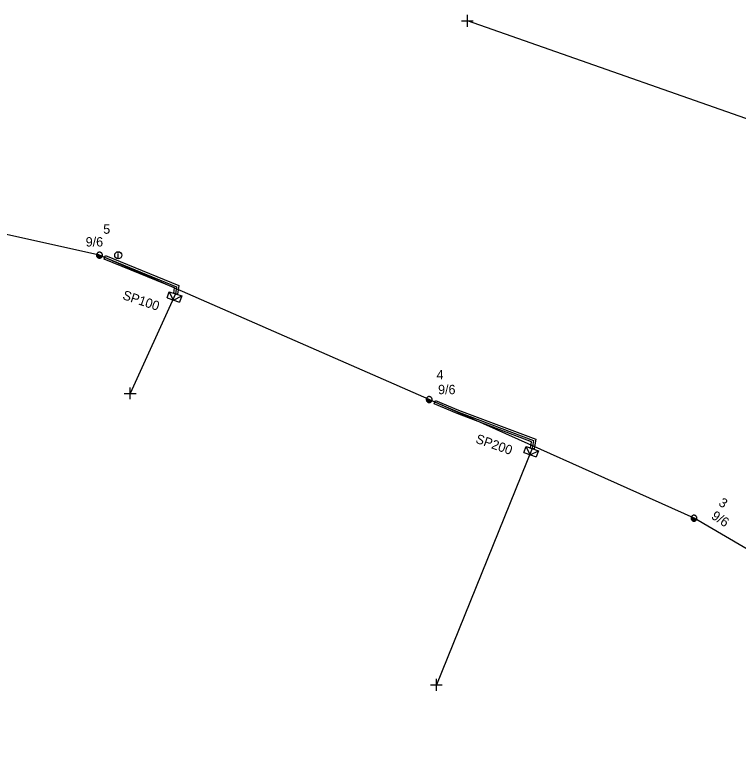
# Model space of a CAD drawing. Extents: x -748492 to -735633, y -1146251 to -1139940.
# Drawn here: x -740584.3 to -740507.1, y -1145456.6 to -1145376.8 of the extents above; entities that cross this region are included whole.
import ezdxf

# ---------------------------------------------------------------- set-up
doc = ezdxf.new("R2010")
doc.units = 0
for name, color, linetype in [('Vrstva 1', 7, 'Continuous'), ('Vrstva 10', 7, 'Continuous'), ('Vrstva 12', 7, 'Continuous'), ('Vrstva 13', 7, 'Continuous'), ('Vrstva 14', 7, 'Continuous'), ('Vrstva 2', 7, 'Continuous'), ('Vrstva 20', 7, 'Continuous'), ('Vrstva 31', 7, 'Continuous'), ('Vrstva 33', 7, 'Continuous'), ('Vrstva 34', 7, 'Continuous'), ('Vrstva 36', 7, 'Continuous'), ('Vrstva 52', 7, 'Continuous'), ('Vrstva 59', 7, 'Continuous'), ('Vrstva 9', 7, 'Continuous')]:
    doc.layers.add(name, color=color, linetype=linetype)

# ---------------------------------------------------------------- blocks, each defined once
blk = doc.blocks.new('NN440')
at = {"layer": 'Vrstva 2'}
for points in [[(0.63, 0), (0.63, 0.06), (0.62, 0.13), (0.6, 0.19), (0.58, 0.25), (0.55, 0.31), (0.51, 0.37), (0.47, 0.42), (0.42, 0.46), (0.37, 0.51), (0.32, 0.54), (0.26, 0.57), (0.2, 0.59), (0.13, 0.61), (0.07, 0.62), (0, 0.63), (-0.06, 0.62), (-0.13, 0.61), (-0.19, 0.59), (-0.26, 0.57), (-0.31, 0.54), (-0.37, 0.51), (-0.42, 0.46), (-0.47, 0.42), (-0.51, 0.37), (-0.54, 0.31), (-0.57, 0.25), (-0.6, 0.19), (-0.62, 0.13), (-0.63, 0.06), (-0.63, 0), (-0.63, -0.07), (-0.62, -0.14), (-0.6, -0.2), (-0.57, -0.26), (-0.54, -0.32), (-0.51, -0.37), (-0.47, -0.43), (-0.42, -0.47), (-0.37, -0.51), (-0.31, -0.55), (-0.26, -0.58), (-0.19, -0.6), (-0.13, -0.62), (-0.06, -0.63), (0, -0.63), (0.07, -0.63), (0.13, -0.62), (0.2, -0.6), (0.26, -0.58), (0.32, -0.55), (0.37, -0.51), (0.42, -0.47), (0.47, -0.43), (0.51, -0.37), (0.55, -0.32), (0.58, -0.26), (0.6, -0.2), (0.62, -0.14), (0.63, -0.07), (0.63, 0)], [(-0.63, 0), (0.63, 0)], [(-0.6, -0.18), (0.57, -0.18)], [(-0.51, -0.32), (0.5, -0.32)], [(-0.37, -0.47), (0.35, -0.47)]]:
    blk.add_lwpolyline(points, dxfattribs=at)
blk = doc.blocks.new('NN770')
at = {"layer": 'Vrstva 10'}
for p, q in [((0.002, 0.187), (0.002, 0.263)), ((0.002, -0.276), (0.002, 0.111))]:
    blk.add_line(p, q, dxfattribs=at)
blk.add_circle((0, -0.008), 0.375, dxfattribs=at)
blk = doc.blocks.new('NN800')
at = {"layer": 'Vrstva 1'}
for points in [[(-0.442, 0.442), (0.442, -0.442)], [(-0.442, -0.442), (0.442, 0.442)]]:
    blk.add_lwpolyline(points, dxfattribs=at)
blk = doc.blocks.new('NN630')
at = {"layer": 'Vrstva 9'}
for points in [[(-0.003, -0.7), (-0.703, 0)], [(-0.703, -0.7), (-0.703, 0), (0.697, 0), (0.697, -0.7)], [(-0.703, -0.7), (0.697, -0.7)], [(-0.003, -0.7), (0.697, 0)]]:
    blk.add_lwpolyline(points, dxfattribs=at)

msp = doc.modelspace()

# ---------------------------------------------------------------- linework, layer by layer
at = {"layer": 'Vrstva 1'}
for points in [[(-740511.819, -1145430.459), (-740540.07, -1145417.8), (-740575.25, -1145402.39), (-740607.81, -1145395.17), (-740640.601, -1145387.661)], [(-740451.452, -1145456.597), (-740452.051, -1145455.71), (-740489.418, -1145443.538), (-740511.819, -1145430.459)]]:
    msp.add_lwpolyline(points, dxfattribs=at)
at = {"layer": 'Vrstva 20'}
for points in [[(-740574.593, -1145402.445), (-740566.797, -1145405.645), (-740566.943, -1145406.552), (-740567.327, -1145406.45), (-740567.243, -1145405.895), (-740574.739, -1145402.819)], [(-740539.395, -1145417.888), (-740536.945, -1145418.935), (-740528.705, -1145422.041), (-740528.883, -1145423.064), (-740529.277, -1145422.996), (-740529.155, -1145422.299), (-740537.095, -1145419.305), (-740539.546, -1145418.249)]]:
    msp.add_lwpolyline(points, close=True, dxfattribs=at)
at = {"layer": 'Vrstva 52'}
for points in [[(-740575.25, -1145402.39), (-740567.02, -1145405.77), (-740567.14, -1145406.52)], [(-740540.07, -1145417.8), (-740537.02, -1145419.12), (-740528.93, -1145422.17), (-740529.08, -1145423.03)]]:
    msp.add_lwpolyline(points, dxfattribs=at)
at = {"layer": 'Vrstva 59'}
for points in [[(-740498.888, -1145390.393), (-740536, -1145377.38)], [(-740567.139, -1145406.519), (-740571.979, -1145417.154)], [(-740529.079, -1145423.03), (-740539.31, -1145448.25)]]:
    msp.add_lwpolyline(points, dxfattribs=at)

# ---------------------------------------------------------------- block references
at = {"layer": 'Vrstva 13', "xscale": 0.5}
for p, yscale, rotation in [((-740575.25, -1145402.39), 0.5, -23.655002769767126), ((-740540.07, -1145417.8), 0.5000000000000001, -24.13668875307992), ((-740511.819, -1145430.459), 0.5, -33.421297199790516)]:
    msp.add_blockref('NN440', p, dxfattribs=dict(at, yscale=yscale, rotation=rotation))
at = {"layer": 'Vrstva 31'}
for p, rotation in [((-740567.139, -1145406.519), -18.63957218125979), ((-740529.079, -1145423.03), -19.331044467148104)]:
    msp.add_blockref('NN630', p, dxfattribs=dict(at, rotation=rotation))
at = {"layer": 'Vrstva 34', "rotation": 45}
for p in [(-740536, -1145377.38), (-740571.979, -1145417.153), (-740539.31, -1145448.25)]:
    msp.add_blockref('NN800', p, dxfattribs=at)
at = {"layer": 'Vrstva 36'}
msp.add_blockref('NN770', (-740573.25, -1145402.39), dxfattribs=at)

# ---------------------------------------------------------------- texts
at = {"layer": 'Vrstva 12'}
for p in [(-740576.721, -1145401.468), (-740539.125, -1145417.23)]:
    msp.add_text('9/6', height=1, dxfattribs=at).set_placement(p)
msp.add_text('9/6', height=1, rotation=326.579, dxfattribs=at).set_placement((-740510.054, -1145430.441))
at = {"layer": 'Vrstva 14'}
for s, p in [('5', (-740574.851, -1145400.108)), ('4', (-740539.295, -1145415.657))]:
    msp.add_text(s, height=1, dxfattribs=at).set_placement(p)
msp.add_text('3', height=1, rotation=326.579, dxfattribs=at).set_placement((-740509.279, -1145429.033))
at = {"layer": 'Vrstva 33'}
for s, rotation, p in [('SP100', 341.36, (-740572.865, -1145407.062)), ('SP200', 340.669, (-740535.2, -1145422.397))]:
    msp.add_text(s, height=1, rotation=rotation, dxfattribs=at).set_placement(p)

doc.saveas('drawing.dxf')
